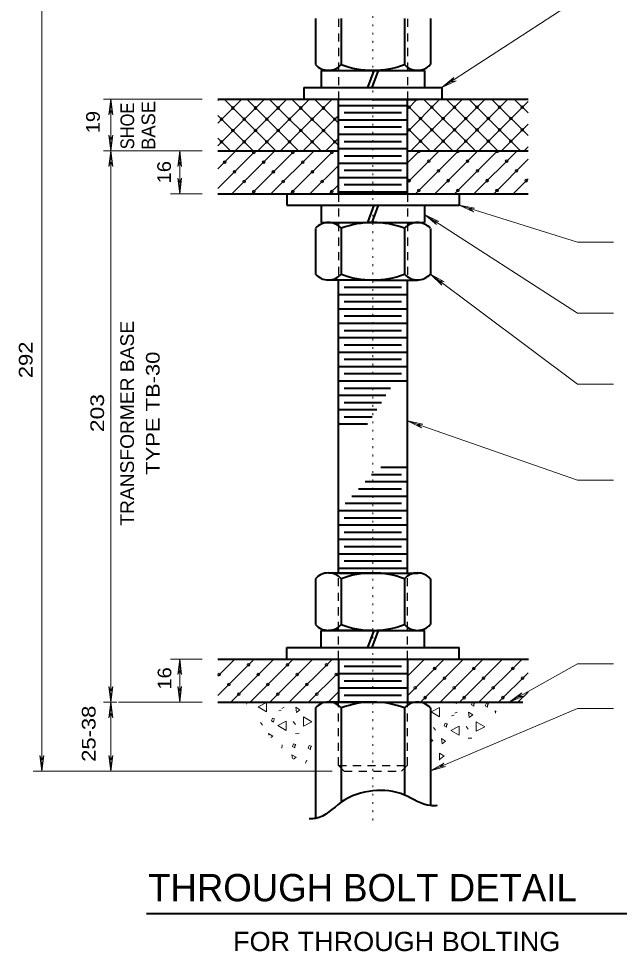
# Model space of a CAD drawing. Extents: x 312583 to 312854, y 144419 to 144597.
# Drawn here: x 312737.1 to 312770.5, y 144513.7 to 144565.6 of the extents above; entities that cross this region are included whole.
import ezdxf
from ezdxf.enums import TextEntityAlignment as Align

# ---------------------------------------------------------------- set-up
doc = ezdxf.new("R2010")
doc.units = 0
doc.header["$LTSCALE"] = 0.3
doc.header["$PDMODE"] = 32
doc.header["$PDSIZE"] = 0.15
doc.linetypes.add('DOTTED', pattern=[1.5, 0.3, -1.2])
doc.linetypes.add('SHORT_DASHED', pattern=[2.7, 1.5, -1.2])
doc.layers.add('1', color=7, linetype='Continuous', lineweight=40)
doc.layers.add('2', color=7, linetype='Continuous', lineweight=13)

msp = doc.modelspace()

# ---------------------------------------------------------------- linework, layer by layer
at = {"layer": '1', "linetype": 'DOTTED', "lineweight": 13}
msp.add_line((312756.7916, 144520.979), (312756.7916, 144569.8846), dxfattribs=at)
at = {"layer": '1'}
for p, q in [((312753.6022, 144565.5606), (312753.6022, 144563.0076)), ((312755.0359, 144565.5606), (312755.0359, 144563.0076)), ((312755.0359, 144565.5606), (312755.0359, 144563.0076)), ((312758.5472, 144565.5606), (312758.5472, 144563.0076)), ((312759.9886, 144565.5606), (312759.9886, 144563.0076)), ((312753.9166, 144562.6856), (312753.9166, 144561.7273)), ((312753.9166, 144562.6856), (312759.6666, 144562.6856)), ((312756.5079, 144561.7273), (312756.8606, 144562.6856)), ((312756.7456, 144561.7273), (312757.0982, 144562.6856)), ((312759.6666, 144562.6856), (312759.6666, 144561.7273)), ((312752.9582, 144561.7273), (312760.6249, 144561.7273)), ((312752.9582, 144561.7273), (312752.9582, 144561.0833)), ((312753.9166, 144561.7273), (312759.6666, 144561.7273)), ((312760.6249, 144561.7273), (312760.6249, 144561.0833)), ((312748.1666, 144561.0833), (312765.4166, 144561.0833)), ((312754.8749, 144555.8163), (312754.8749, 144561.0833)), ((312754.8749, 144560.7383), (312758.7082, 144560.7383)), ((312756.7916, 144561.068), (312759.2679, 144561.068)), ((312758.7082, 144555.8163), (312758.7082, 144561.0833)), ((312755.1969, 144560.3396), (312758.3862, 144560.3396)), ((312754.8749, 144559.941), (312758.7082, 144559.941)), ((312754.8749, 144559.136), (312758.7082, 144559.136)), ((312755.1969, 144559.5423), (312758.3862, 144559.5423)), ((312755.1969, 144558.7373), (312758.3862, 144558.7373)), ((312748.1666, 144558.2083), (312754.8749, 144558.2083)), ((312754.8749, 144558.3386), (312758.7082, 144558.3386)), ((312758.7082, 144558.2083), (312765.4166, 144558.2083)), ((312754.8749, 144557.5336), (312758.7082, 144557.5336)), ((312755.1969, 144557.94), (312758.3862, 144557.94)), ((312755.1969, 144557.135), (312758.3862, 144557.135)), ((312754.8749, 144556.7363), (312758.7082, 144556.7363)), ((312754.8749, 144555.9313), (312758.7082, 144555.9313)), ((312755.1969, 144556.3376), (312758.3862, 144556.3376)), ((312748.1666, 144555.8163), (312765.4166, 144555.8163)), ((312751.9999, 144555.8163), (312751.9999, 144555.18)), ((312761.5832, 144555.8163), (312761.5832, 144555.18)), ((312751.9999, 144555.18), (312761.5832, 144555.18)), ((312753.9166, 144555.18), (312753.9166, 144554.2216)), ((312756.5079, 144554.2216), (312756.8606, 144555.18)), ((312756.7456, 144554.2216), (312757.0982, 144555.18)), ((312759.6666, 144555.18), (312759.6666, 144554.2216)), ((312753.6022, 144553.8996), (312753.6022, 144551.3466)), ((312753.9166, 144554.2216), (312759.6666, 144554.2216)), ((312755.0359, 144553.8996), (312755.0359, 144551.3466)), ((312755.0359, 144553.8996), (312755.0359, 144551.3466)), ((312758.5472, 144553.8996), (312758.5472, 144551.3466)), ((312759.9886, 144553.8996), (312759.9886, 144551.3466)), ((312756.7916, 144551.0246), (312754.3152, 144551.0246)), ((312754.8749, 144534.733), (312754.8749, 144551.0246)), ((312756.7916, 144551.0246), (312759.2679, 144551.0246)), ((312758.7082, 144534.733), (312758.7082, 144551.0246)), ((312754.8749, 144550.2273), (312758.7082, 144550.2273)), ((312755.1969, 144550.626), (312758.3862, 144550.626)), ((312755.1969, 144549.8286), (312758.3862, 144549.8286)), ((312754.8749, 144549.43), (312758.7082, 144549.43)), ((312755.1969, 144549.0313), (312758.3862, 144549.0313)), ((312754.8749, 144548.625), (312758.7082, 144548.625)), ((312755.1969, 144548.2263), (312758.3862, 144548.2263)), ((312754.8749, 144547.8276), (312758.7082, 144547.8276)), ((312755.1969, 144547.429), (312758.3862, 144547.429)), ((312754.8749, 144547.0226), (312758.7082, 144547.0226)), ((312755.1969, 144546.624), (312758.3862, 144546.624)), ((312754.8749, 144546.2253), (312758.7082, 144546.2253)), ((312755.1969, 144545.8266), (312758.3862, 144545.8266)), ((312754.8749, 144545.4203), (312758.7082, 144545.4203)), ((312754.8749, 144544.623), (312757.5199, 144544.623)), ((312755.1969, 144545.0216), (312757.7729, 144545.0216)), ((312755.1969, 144544.2243), (312757.2669, 144544.2243)), ((312754.8749, 144543.818), (312757.0062, 144543.818)), ((312754.8749, 144543.0206), (312756.4926, 144543.0206)), ((312755.1969, 144543.4193), (312756.7532, 144543.4193)), ((312757.2286, 144540.6133), (312758.7082, 144540.6133)), ((312756.7226, 144540.2146), (312758.3862, 144540.2146)), ((312755.9866, 144539.4096), (312758.3862, 144539.4096)), ((312756.3546, 144539.816), (312758.7082, 144539.816)), ((312755.6186, 144539.011), (312758.7082, 144539.011)), ((312755.2429, 144538.6123), (312758.3862, 144538.6123)), ((312754.8749, 144538.2136), (312758.7082, 144538.2136)), ((312755.1969, 144537.8073), (312758.3862, 144537.8073)), ((312754.8749, 144537.4086), (312758.7082, 144537.4086)), ((312755.1969, 144537.01), (312758.3862, 144537.01)), ((312754.8749, 144536.6113), (312758.7082, 144536.6113)), ((312754.8749, 144535.8063), (312758.7082, 144535.8063)), ((312755.1969, 144536.205), (312758.3862, 144536.205)), ((312755.1969, 144535.4076), (312758.3862, 144535.4076)), ((312756.7916, 144534.733), (312754.3152, 144534.733)), ((312754.8749, 144535.009), (312758.7082, 144535.009)), ((312754.8749, 144534.733), (312759.3139, 144534.733)), ((312756.7916, 144534.733), (312759.2679, 144534.733)), ((312753.6022, 144534.4186), (312753.6022, 144531.8656)), ((312755.0359, 144534.4186), (312755.0359, 144531.8656)), ((312755.0359, 144534.4186), (312755.0359, 144531.8656)), ((312758.5472, 144534.4186), (312758.5472, 144531.8656)), ((312759.9886, 144534.4186), (312759.9886, 144531.8656)), ((312753.9166, 144531.5436), (312759.6666, 144531.5436)), ((312753.9166, 144530.5853), (312753.9166, 144531.5436)), ((312756.7916, 144531.5436), (312754.3152, 144531.5436)), ((312756.5079, 144530.5853), (312756.8606, 144531.5436)), ((312756.7456, 144530.5853), (312757.0982, 144531.5436)), ((312756.7916, 144531.5436), (312759.2679, 144531.5436)), ((312759.6666, 144530.5853), (312759.6666, 144531.5436)), ((312751.9999, 144530.5853), (312761.5832, 144530.5853)), ((312751.9999, 144529.949), (312751.9999, 144530.5853)), ((312761.5832, 144529.949), (312761.5832, 144530.5853)), ((312748.1666, 144529.949), (312765.4396, 144529.949)), ((312754.8749, 144529.949), (312754.8749, 144527.5493)), ((312755.1969, 144529.5503), (312758.3862, 144529.5503)), ((312758.7082, 144529.949), (312758.7082, 144527.5493)), ((312754.8749, 144529.1516), (312758.7082, 144529.1516)), ((312755.1969, 144528.7453), (312758.3862, 144528.7453)), ((312754.8749, 144528.3466), (312758.7082, 144528.3466)), ((312755.1969, 144527.948), (312758.3862, 144527.948)), ((312748.1666, 144527.5493), (312765.1252, 144527.5493)), ((312756.7916, 144527.5493), (312754.3152, 144527.5493)), ((312754.8749, 144527.5493), (312759.3139, 144527.5493)), ((312756.7916, 144527.5493), (312759.2679, 144527.5493)), ((312753.6022, 144527.235), (312753.6022, 144521.0863)), ((312755.0359, 144527.235), (312755.0359, 144521.991)), ((312755.0359, 144527.235), (312755.0359, 144524.682)), ((312758.5472, 144527.235), (312758.5472, 144522.3896)), ((312759.9886, 144527.235), (312759.9886, 144521.7993))]:
    msp.add_line(p, q, dxfattribs=at)
at = {"layer": '1', "linetype": 'SHORT_DASHED', "lineweight": 25}
for p, q in [((312754.8749, 144565.553), (312754.8749, 144561.0833)), ((312758.7082, 144565.553), (312758.7082, 144561.0833)), ((312754.8749, 144555.8163), (312754.8749, 144551.0246)), ((312758.7082, 144555.8163), (312758.7082, 144551.0246)), ((312754.8749, 144529.949), (312754.8749, 144534.733)), ((312758.7082, 144529.949), (312758.7082, 144534.733)), ((312754.8749, 144524.038), (312754.8749, 144527.5493)), ((312758.7082, 144524.038), (312758.7082, 144527.5493)), ((312754.8749, 144524.038), (312755.1969, 144523.716)), ((312754.8749, 144524.038), (312758.7082, 144524.038)), ((312758.3862, 144523.716), (312758.7082, 144524.038)), ((312755.1969, 144523.716), (312758.3862, 144523.716))]:
    msp.add_line(p, q, dxfattribs=at)
at = {"layer": '1'}
for centre, radius, start, end in [((312754.3161, 144563.6548), 0.9679, 222.07502, 317.92498), ((312756.7908, 144567.6762), 4.9893, 249.39031, 290.60969), ((312759.2655, 144563.6548), 0.9679, 222.07502, 317.92498), ((312754.3161, 144553.255), 0.9679, 42.07502, 137.92498), ((312756.7908, 144549.2336), 4.9893, 69.39031, 110.60969), ((312759.2655, 144553.255), 0.9679, 42.07502, 137.92498), ((312754.3161, 144551.9976), 0.9679, 222.07502, 317.92498), ((312756.7908, 144556.019), 4.9893, 249.39031, 290.60969), ((312759.2655, 144551.9976), 0.9679, 222.07502, 317.92498), ((312754.3161, 144533.7701), 0.9679, 42.07502, 137.92498), ((312756.7908, 144529.7487), 4.9893, 69.39031, 110.60969), ((312759.2655, 144533.7701), 0.9679, 42.07502, 137.92498), ((312754.3161, 144532.5128), 0.9679, 222.07502, 317.92498), ((312756.7908, 144536.5342), 4.9893, 249.39031, 290.60969), ((312759.2655, 144532.5128), 0.9679, 222.07502, 317.92498), ((312754.3161, 144526.5865), 0.9679, 42.07502, 137.92498), ((312756.7908, 144522.5651), 4.9893, 69.39031, 110.60969), ((312759.2655, 144526.5865), 0.9679, 42.07502, 137.92498)]:
    msp.add_arc(centre, radius, start, end, dxfattribs=at)
msp.add_spline([(312760.3642, 144521.7993), (312759.9886, 144521.7993), (312758.5472, 144522.3896), (312756.7916, 144522.6196), (312755.0359, 144521.991), (312753.6022, 144521.0863), (312753.2572, 144521.0633)], degree=3, dxfattribs=at)
at = {"layer": '2'}
for p, q in [((312738.3839, 144523.716), (312738.3839, 144567.7916)), ((312760.6249, 144561.7273), (312761.2919, 144562.287)), ((312761.2919, 144562.287), (312761.1232, 144562.0493)), ((312760.6249, 144561.7273), (312761.4146, 144562.1106)), ((312761.4146, 144562.1106), (312761.1232, 144562.0493)), ((312747.2926, 144561.0833), (312741.8109, 144561.0833)), ((312742.2172, 144561.0833), (312742.1099, 144560.217)), ((312742.2172, 144558.2083), (312742.2172, 144561.0833)), ((312742.2172, 144561.0833), (312742.3246, 144560.217)), ((312748.1666, 144558.492), (312750.7579, 144561.0833)), ((312748.1666, 144559.7493), (312749.5006, 144561.0833)), ((312748.1666, 144561.0066), (312748.2432, 144561.0833)), ((312751.3942, 144558.2083), (312748.5192, 144561.0833)), ((312749.1402, 144558.2083), (312752.0152, 144561.0833)), ((312752.6516, 144558.2083), (312749.7766, 144561.0833)), ((312750.3976, 144558.2083), (312753.2726, 144561.0833)), ((312753.9089, 144558.2083), (312751.0339, 144561.0833)), ((312751.6549, 144558.2083), (312754.5299, 144561.0833)), ((312754.8749, 144558.4996), (312752.2912, 144561.0833)), ((312754.8749, 144559.757), (312753.5486, 144561.0833)), ((312754.8749, 144561.0143), (312754.8059, 144561.0833)), ((312758.7082, 144559.274), (312760.5176, 144561.0833)), ((312758.7082, 144560.5313), (312759.2602, 144561.0833)), ((312761.2306, 144558.2083), (312758.7082, 144560.7306)), ((312758.9076, 144558.2083), (312761.7749, 144561.0833)), ((312762.4879, 144558.2083), (312759.6129, 144561.0833)), ((312760.1649, 144558.2083), (312763.0322, 144561.0833)), ((312763.7452, 144558.2083), (312760.8702, 144561.0833)), ((312761.4222, 144558.2083), (312764.2896, 144561.0833)), ((312765.0026, 144558.2083), (312762.1276, 144561.0833)), ((312762.6796, 144558.2083), (312765.4166, 144560.9453)), ((312765.4166, 144559.0593), (312763.3849, 144561.0833)), ((312765.4166, 144560.3166), (312764.6422, 144561.0833)), ((312742.1099, 144560.217), (312742.2172, 144560.493)), ((312742.3246, 144560.217), (312742.2172, 144560.493)), ((312750.1369, 144558.2083), (312748.1666, 144560.1786)), ((312752.9122, 144558.2083), (312754.8749, 144560.171)), ((312763.9369, 144558.2083), (312765.4166, 144559.688)), ((312742.1099, 144559.0746), (312742.2172, 144558.7986)), ((312742.2172, 144558.2083), (312742.1099, 144559.0746)), ((312742.3246, 144559.0746), (312742.2172, 144558.7986)), ((312742.2172, 144558.2083), (312742.3246, 144559.0746)), ((312759.9732, 144558.2083), (312758.7082, 144559.4733)), ((312748.8796, 144558.2083), (312748.1666, 144558.9213)), ((312754.1772, 144558.2083), (312754.8749, 144558.9136)), ((312747.2926, 144558.2083), (312741.8109, 144558.2083)), ((312742.2172, 144558.2083), (312742.1099, 144557.342)), ((312742.2172, 144558.2083), (312742.3246, 144557.342)), ((312746.0506, 144558.2083), (312745.9432, 144557.342)), ((312746.0506, 144555.8163), (312746.0506, 144558.2083)), ((312746.0506, 144558.2083), (312746.1579, 144557.342)), ((312748.1666, 144556.1153), (312750.2596, 144558.2083)), ((312748.1666, 144557.204), (312749.1786, 144558.2083)), ((312748.9486, 144555.8163), (312751.3482, 144558.2083)), ((312750.0372, 144555.8163), (312752.4292, 144558.2083)), ((312751.1182, 144555.8163), (312753.5179, 144558.2083)), ((312752.1992, 144555.8163), (312754.5989, 144558.2083)), ((312758.7159, 144558.2083), (312758.7082, 144558.216)), ((312758.7082, 144556.4526), (312760.4716, 144558.2083)), ((312758.7082, 144557.5413), (312759.3829, 144558.2083)), ((312759.1529, 144555.8163), (312761.5526, 144558.2083)), ((312760.2416, 144555.8163), (312762.6336, 144558.2083)), ((312761.3226, 144555.8163), (312763.7146, 144558.2083)), ((312762.4112, 144555.8163), (312764.8032, 144558.2083)), ((312765.1942, 144558.2083), (312765.4166, 144558.4306)), ((312742.1099, 144557.342), (312742.2172, 144557.618)), ((312742.3246, 144557.342), (312742.2172, 144557.618)), ((312745.9432, 144557.342), (312746.0506, 144557.618)), ((312746.1579, 144557.342), (312746.0506, 144557.618)), ((312763.4922, 144555.8086), (312765.4166, 144557.7406)), ((312753.2879, 144555.8163), (312754.8749, 144557.4033)), ((312745.9432, 144556.6826), (312746.0506, 144556.4066)), ((312746.0506, 144555.8163), (312745.9432, 144556.6826)), ((312746.1579, 144556.6826), (312746.0506, 144556.4066)), ((312746.0506, 144555.8163), (312746.1579, 144556.6826)), ((312764.5732, 144555.8086), (312765.4166, 144556.652)), ((312754.3689, 144555.8163), (312754.8749, 144556.3223)), ((312747.2926, 144555.8163), (312745.5369, 144555.8163)), ((312761.5832, 144555.18), (312762.3806, 144554.8196)), ((312761.5832, 144555.18), (312762.4419, 144555.0266)), ((312762.4419, 144555.0266), (312762.1506, 144555.0036)), ((312762.3806, 144554.8196), (312762.1506, 144555.0036)), ((312759.6666, 144554.6663), (312768.1689, 144549.1923)), ((312759.6666, 144554.6663), (312760.3336, 144554.1066)), ((312759.6666, 144554.6663), (312760.4486, 144554.283)), ((312760.3336, 144554.1066), (312760.1649, 144554.3443)), ((312760.4486, 144554.283), (312760.1649, 144554.3443)), ((312759.9886, 144551.3466), (312768.1689, 144545.244)), ((312759.9886, 144551.3466), (312760.6172, 144550.741)), ((312759.9886, 144551.3466), (312760.7476, 144550.9173)), ((312760.6172, 144550.741), (312760.4562, 144550.994)), ((312760.7476, 144550.9173), (312760.4562, 144550.994)), ((312768.1689, 144549.1923), (312770.1699, 144549.1923)), ((312768.1689, 144545.244), (312770.1699, 144545.244)), ((312758.7082, 144543.1893), (312768.1689, 144539.9003)), ((312758.7082, 144543.1893), (312759.4902, 144542.806)), ((312758.7082, 144543.1893), (312759.5669, 144543.0053)), ((312759.5669, 144543.0053), (312759.2679, 144542.9976)), ((312759.4902, 144542.806), (312759.2679, 144542.9976)), ((312768.1689, 144539.9003), (312770.1699, 144539.9003)), ((312747.2926, 144529.949), (312745.5369, 144529.949)), ((312746.0506, 144529.949), (312745.9432, 144529.0826)), ((312746.0506, 144527.5493), (312746.0506, 144529.949)), ((312746.0506, 144529.949), (312746.1579, 144529.0826)), ((312748.1666, 144527.9173), (312750.1982, 144529.949)), ((312748.1666, 144529.006), (312749.1096, 144529.949)), ((312748.8872, 144527.5493), (312751.2792, 144529.949)), ((312749.9682, 144527.5493), (312752.3679, 144529.949)), ((312751.0569, 144527.5493), (312753.4489, 144529.949)), ((312752.1379, 144527.5493), (312754.5376, 144529.949)), ((312758.7082, 144527.9096), (312760.7476, 144529.949)), ((312758.7082, 144528.9906), (312759.6666, 144529.949)), ((312759.4366, 144527.5493), (312761.8286, 144529.949)), ((312760.5252, 144527.5493), (312762.9172, 144529.949)), ((312761.6062, 144527.5493), (312763.9982, 144529.949)), ((312762.6872, 144527.5493), (312765.0869, 144529.949)), ((312764.3586, 144527.5493), (312768.1689, 144529.6806)), ((312768.1689, 144529.6806), (312770.1699, 144529.6806)), ((312745.9432, 144529.0826), (312746.0506, 144529.3586)), ((312746.1579, 144529.0826), (312746.0506, 144529.3586)), ((312753.2189, 144527.5493), (312754.8749, 144529.2053)), ((312763.7682, 144527.5493), (312765.4166, 144529.19)), ((312742.1099, 144528.4156), (312742.2172, 144528.1396)), ((312742.2172, 144527.5493), (312742.1099, 144528.4156)), ((312742.3246, 144528.4156), (312742.2172, 144528.1396)), ((312742.2172, 144527.5493), (312742.3246, 144528.4156)), ((312745.9432, 144528.4156), (312746.0506, 144528.1396)), ((312746.0506, 144527.5493), (312745.9432, 144528.4156)), ((312746.1579, 144528.4156), (312746.0506, 144528.1396)), ((312746.0506, 144527.5493), (312746.1579, 144528.4156)), ((312754.3076, 144527.5493), (312754.8749, 144528.1243)), ((312764.3586, 144527.5493), (312765.0639, 144528.0706)), ((312764.8569, 144527.5493), (312765.4166, 144528.109)), ((312765.0639, 144528.0706), (312764.8722, 144527.8406)), ((312742.5546, 144527.5493), (312741.8109, 144527.5493)), ((312742.2172, 144527.5493), (312742.1099, 144526.683)), ((312742.2172, 144527.5493), (312742.3246, 144526.683)), ((312747.2926, 144527.5493), (312742.6542, 144527.5493)), ((312749.8149, 144527.5493), (312749.7689, 144527.4343)), ((312761.3149, 144527.5493), (312761.4376, 144527.4726)), ((312761.4376, 144527.4726), (312761.4376, 144527.5493)), ((312762.4036, 144527.442), (312762.4572, 144527.5263)), ((312764.3586, 144527.5493), (312765.1712, 144527.879)), ((312765.1712, 144527.879), (312764.8722, 144527.8406)), ((312742.1099, 144526.683), (312742.2172, 144526.959)), ((312742.3246, 144526.683), (312742.2172, 144526.959)), ((312751.5552, 144527.074), (312751.7009, 144527.097)), ((312751.7239, 144527.2043), (312751.8542, 144527.2733)), ((312759.9886, 144523.7313), (312768.1689, 144527.2043)), ((312761.3379, 144526.936), (312761.4682, 144527.005)), ((312768.1689, 144527.2043), (312770.1699, 144527.2043)), ((312750.5509, 144526.4146), (312750.6582, 144526.2766)), ((312752.3602, 144526.4683), (312752.4829, 144526.315)), ((312761.1692, 144526.798), (312761.3149, 144526.8286)), ((312760.1572, 144526.1386), (312760.2646, 144526.0006)), ((312761.9742, 144526.2), (312762.0969, 144526.0466)), ((312752.4829, 144525.8166), (312752.6899, 144525.832)), ((312762.0892, 144525.5483), (312762.2886, 144525.556)), ((312751.7239, 144524.9886), (312751.7469, 144525.1726)), ((312738.2766, 144524.5823), (312738.3839, 144524.3063)), ((312738.3839, 144523.716), (312738.2766, 144524.5823)), ((312738.4912, 144524.5823), (312738.3839, 144524.3063)), ((312738.3839, 144523.716), (312738.4912, 144524.5823)), ((312742.1099, 144524.5823), (312742.2172, 144524.3063)), ((312742.2172, 144523.716), (312742.1099, 144524.5823)), ((312742.3246, 144524.5823), (312742.2172, 144524.3063)), ((312742.2172, 144523.716), (312742.3246, 144524.5823)), ((312753.1192, 144524.3293), (312753.0426, 144524.153)), ((312760.4716, 144524.337), (312760.7476, 144524.567)), ((312760.4869, 144524.7203), (312760.4869, 144524.3216)), ((312760.7399, 144524.567), (312760.4869, 144524.7203)), ((312759.9886, 144523.7313), (312760.7399, 144524.1683)), ((312759.9886, 144523.7313), (312760.8242, 144523.969)), ((312760.7399, 144524.1683), (312760.5329, 144523.9613)), ((312760.8242, 144523.969), (312760.5329, 144523.9613)), ((312754.5299, 144523.716), (312737.9086, 144523.716))]:
    msp.add_line(p, q, dxfattribs=at)
at = {"layer": '2', "lineweight": 40}
msp.add_line((312744.2039, 144515.8008), (312771.1336, 144515.8008), dxfattribs=at)
at = {"layer": '2'}
for points in [[(312760.6249, 144561.7273), (312768.1689, 144566.6493), (312770.1699, 144566.6493)], [(312742.2172, 144523.716), (312742.2172, 144527.5493), (312742.2172, 144558.2083)], [(312761.5832, 144555.18), (312768.1689, 144553.1406), (312770.1699, 144553.1406)], [(312762.3346, 144527.557), (312762.3346, 144527.5493), (312762.2809, 144527.4113), (312762.4036, 144527.3346), (312762.4036, 144527.442)], [(312762.4572, 144527.5263), (312762.3652, 144527.5493), (312762.3346, 144527.557)], [(312763.6532, 144527.028), (312763.5919, 144527.0663), (312763.5996, 144526.9436)], [(312751.1182, 144525.579), (312751.2256, 144525.6633), (312750.9879, 144525.8013), (312751.0032, 144525.717)], [(312759.9886, 144525.326), (312760.1266, 144525.4256), (312759.9886, 144525.51)], [(312752.3756, 144524.3753), (312752.5289, 144524.4903), (312752.2912, 144524.6283), (312752.3219, 144524.4213)]]:
    msp.add_lwpolyline(points, dxfattribs=at)
for points in [[(312750.8806, 144527.0126), (312750.8806, 144527.5263), (312750.4206, 144527.2963)], [(312763.1702, 144527.3883), (312763.2162, 144527.4726), (312763.1012, 144527.5033), (312763.0399, 144527.35), (312763.1702, 144527.281)], [(312752.5366, 144526.9743), (312752.7282, 144527.12), (312752.4982, 144527.2656)], [(312760.4946, 144526.7443), (312760.4946, 144527.258), (312760.0269, 144527.0203)], [(312762.1506, 144526.706), (312762.3422, 144526.8516), (312762.1122, 144526.9896)], [(312751.2792, 144526.545), (312751.3252, 144526.6293), (312751.2026, 144526.6676), (312751.1489, 144526.5143), (312751.2716, 144526.4376)], [(312751.9769, 144525.9776), (312751.9769, 144526.4913), (312751.5092, 144526.2536)], [(312752.9276, 144526.7366), (312752.9276, 144526.223), (312753.3952, 144526.453)], [(312760.8856, 144526.269), (312760.9316, 144526.3533), (312760.8166, 144526.3916), (312760.7552, 144526.2383), (312760.8856, 144526.1693)], [(312762.5416, 144526.4606), (312762.5416, 144525.947), (312763.0092, 144526.177)], [(312761.5909, 144525.7093), (312761.5909, 144526.223), (312761.1232, 144525.9853)], [(312760.6402, 144525.2416), (312760.8319, 144525.3873), (312760.6019, 144525.533)], [(312752.4522, 144525.119), (312752.4982, 144525.2033), (312752.3832, 144525.2416), (312752.3219, 144525.0883), (312752.4522, 144525.0193)], [(312753.3262, 144525.027), (312753.3722, 144525.1113), (312753.2496, 144525.142), (312753.1959, 144524.9886), (312753.3186, 144524.9196)]]:
    msp.add_lwpolyline(points, close=True, dxfattribs=at)
for p in [(312749.0099, 144560.5926), (312750.2672, 144560.5926), (312751.5246, 144560.5926), (312752.7819, 144560.5926), (312754.0392, 144560.5926), (312758.8079, 144560.631), (312760.0652, 144560.631), (312761.3226, 144560.631), (312762.5799, 144560.631), (312763.8372, 144560.631), (312765.0946, 144560.631), (312759.4366, 144560.0023), (312760.6939, 144560.0023), (312761.9512, 144560.0023), (312763.2086, 144560.0023), (312764.4659, 144560.0023), (312748.3812, 144559.964), (312749.6386, 144559.964), (312750.8959, 144559.964), (312752.1532, 144559.964), (312753.4106, 144559.964), (312754.6679, 144559.964), (312749.0099, 144559.3353), (312750.2672, 144559.3353), (312751.5246, 144559.3353), (312752.7819, 144559.3353), (312754.0392, 144559.3353), (312758.8079, 144559.3736), (312760.0652, 144559.3736), (312761.3226, 144559.3736), (312762.5799, 144559.3736), (312763.8372, 144559.3736), (312765.0946, 144559.3736), (312748.3812, 144558.7066), (312749.6386, 144558.7066), (312750.8959, 144558.7066), (312752.1532, 144558.7066), (312753.4106, 144558.7066), (312754.6679, 144558.7066), (312759.4366, 144558.745), (312760.6939, 144558.745), (312761.9512, 144558.745), (312763.2086, 144558.745), (312764.4659, 144558.745), (312750.1752, 144558.124), (312752.3449, 144558.124), (312754.5146, 144558.124), (312759.3522, 144558.1776), (312761.5219, 144558.1776), (312763.6916, 144558.1776), (312748.5499, 144557.5796), (312750.7196, 144557.5796), (312752.8892, 144557.5796), (312759.8966, 144557.6333), (312762.0586, 144557.6333), (312764.2282, 144557.6333), (312749.0942, 144557.043), (312751.2562, 144557.043), (312753.4259, 144557.043), (312760.4332, 144557.0966), (312762.6029, 144557.0966), (312764.7726, 144557.0966), (312749.6309, 144556.4986), (312751.8006, 144556.4986), (312753.9702, 144556.4986), (312758.8079, 144556.5523), (312760.9776, 144556.5523), (312763.1472, 144556.5523), (312765.3169, 144556.5523), (312750.1752, 144555.9543), (312752.3449, 144555.9543), (312754.5146, 144555.9543), (312759.3522, 144556.008), (312761.5219, 144556.008), (312763.6916, 144556.008), (312749.8762, 144529.627), (312752.0459, 144529.627), (312754.2079, 144529.627), (312760.2262, 144529.4276), (312762.3959, 144529.4276), (312764.5656, 144529.4276), (312748.2509, 144529.0826), (312750.4206, 144529.0826), (312752.5826, 144529.0826), (312754.7522, 144529.0826), (312760.7706, 144528.8833), (312762.9402, 144528.8833), (312765.1099, 144528.8833), (312748.7876, 144528.5383), (312750.9572, 144528.5383), (312753.1269, 144528.5383), (312749.3319, 144528.0016), (312751.5016, 144528.0016), (312753.6712, 144528.0016), (312759.1452, 144528.3466), (312761.3149, 144528.3466), (312763.4846, 144528.3466), (312759.6896, 144527.8023), (312761.8592, 144527.8023), (312764.0212, 144527.8023)]:
    msp.add_point(p, dxfattribs=at)

# ---------------------------------------------------------------- texts
for s, width, p in [('SHOE', 0.9, (312743.5186, 144558.2982)), ('19 ', 1.1, (312741.6101, 144559.1837)), ('16 ', 1.1, (312745.5639, 144556.3997)), ('TRANSFORMER BASE', 1.05, (312743.5081, 144537.3684)), ('292 ', 1.2, (312737.8689, 144545.5685)), ('TYPE TB-30', 1.2, (312744.9352, 144540.1989)), ('203 ', 1.25, (312741.844, 144542.5677)), ('16 ', 1.1, (312745.585, 144528.2498)), ('25-38', 1.2, (312741.3716, 144524.2367))]:
    msp.add_text(s, height=0.76, rotation=90, dxfattribs=dict(at, width=width)).set_placement(p)
msp.add_text('BASE', height=0.76, rotation=90, dxfattribs=at).set_placement((312744.6897, 144558.268))
msp.add_text('THROUGH BOLT DETAIL', height=1.52, dxfattribs=at).set_placement((312756.2117, 144516.4786), align=Align.CENTER)
at = {"layer": '2', "width": 1.05}
msp.add_text('FOR THROUGH BOLTING', height=1.07, dxfattribs=at).set_placement((312758.1154, 144513.7107), align=Align.CENTER)

doc.saveas('drawing.dxf')
